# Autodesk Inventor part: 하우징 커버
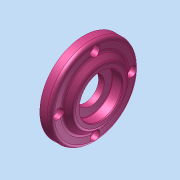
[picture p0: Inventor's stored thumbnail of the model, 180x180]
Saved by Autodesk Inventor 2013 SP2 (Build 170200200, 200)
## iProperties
Created: 2026-01
Part Number: 하우징 커버
Material: Generic
Document SubType Name: Modeling
Designer: a
Density: 1 g/cm^3
Author: a
변환 표준: STEP AP214IS
전처리기: Build: 200, Release: 2013 SP2 Update 6 - Date: Thu 07/17/2014
전송 단위: 밀리미터
불확실성: 0.01
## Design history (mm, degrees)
node "하우징 커버1"
node "솔리드1"
node "기준1"
